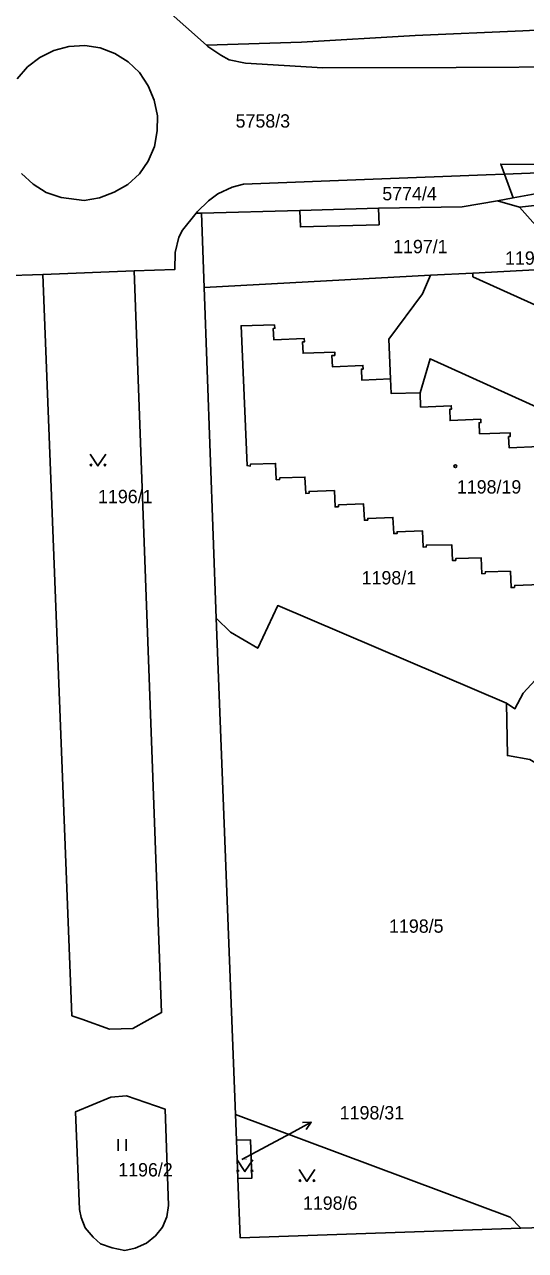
# Model space of a CAD drawing. Extents: x -737240 to -735272, y -1119606 to -1117878.
# Drawn here: x -736364.4 to -736300.4, y -1118991.4 to -1118834.9 of the extents above; entities that cross this region are included whole.
import ezdxf

# ---------------------------------------------------------------- set-up
doc = ezdxf.new("R2010")
doc.units = 0
for name, color, linetype in [('Level 1', 7, 'Continuous'), ('Level 16', 7, 'Continuous'), ('Level 18', 7, 'Continuous'), ('Level 19', 7, 'Continuous'), ('Level 25', 7, 'Continuous'), ('Level 4', 7, 'Continuous')]:
    doc.layers.add(name, color=color, linetype=linetype)

msp = doc.modelspace()

# ---------------------------------------------------------------- linework, layer by layer
at = {"layer": 'Level 1'}
for p, q in [((-736302.01, -1118857.02), (-736279.15, -1118852.89)), ((-736302.01, -1118857.02), (-736303.13, -1118854)), ((-736304.02, -1118857.38), (-736302.01, -1118857.02)), ((-736304.02, -1118857.38), (-736301.2, -1118858.22)), ((-736342.5, -1118858.98), (-736341.8, -1118858.99)), ((-736341.8, -1118858.99), (-736329.24, -1118858.62)), ((-736341.45, -1118868.44), (-736341.8, -1118858.99)), ((-736294.23, -1118865.92), (-736307.17, -1118866.61)), ((-736362.05, -1118866.78), (-736350.38, -1118866.35)), ((-736312.56, -1118866.9), (-736341.45, -1118868.44)), ((-736307.17, -1118866.61), (-736312.56, -1118866.9)), ((-736339.93, -1118910.64), (-736341.45, -1118868.44)), ((-736337.48, -1118973.99), (-736339.93, -1118910.64)), ((-736337.35, -1118977.29), (-736337.48, -1118973.99)), ((-736337.35, -1118977.29), (-736337.16, -1118982.18)), ((-736280.9, -1118987.85), (-736301.04, -1118988.52))]:
    msp.add_line(p, q, dxfattribs=at)
for points in [[(-736341.17, -1118837.53), (-736343.79, -1118835.17), (-736346.04, -1118833.2), (-736346.85, -1118832.56), (-736349.46, -1118831.04), (-736352.7, -1118828.71), (-736353.4, -1118828), (-736355.31, -1118825.68), (-736355.71, -1118824.8), (-736361.77, -1118826.39)], [(-736270.78, -1118834.19), (-736278.9, -1118834.59), (-736300.78, -1118835.7), (-736314.51, -1118836.31), (-736329.03, -1118837.15), (-736341.17, -1118837.53)], [(-736275.1, -1118839.95), (-736287.83, -1118840.38), (-736293.27, -1118840.3), (-736309.28, -1118840.36), (-736326.31, -1118840.44), (-736336.17, -1118839.81), (-736338.26, -1118839.41), (-736339.35, -1118838.81), (-736341.01, -1118837.68), (-736341.17, -1118837.53)], [(-736303.13, -1118854), (-736303.61, -1118852.71), (-736286.16, -1118852.84)], [(-736303.13, -1118854), (-736287.83, -1118853.38), (-736286.16, -1118852.84)], [(-736342.5, -1118858.98), (-736342.35, -1118858.8), (-736340.89, -1118857.4), (-736339.73, -1118856.5), (-736337.88, -1118855.67), (-736336.43, -1118855.25), (-736319.9, -1118854.62), (-736305.45, -1118854.09), (-736303.13, -1118854)], [(-736319.19, -1118858.34), (-736308.54, -1118858.15), (-736304.02, -1118857.38)], [(-736294.02, -1118858.75), (-736296.65, -1118857.69), (-736301.2, -1118858.22)], [(-736371.48, -1118858.67), (-736369.78, -1118860.4), (-736368.64, -1118862.08), (-736368.28, -1118863.06), (-736367.4, -1118866.97), (-736362.05, -1118866.78)], [(-736350.38, -1118866.35), (-736345.22, -1118866.16), (-736345.16, -1118863.99), (-736344.68, -1118862.04), (-736344.22, -1118861.14), (-736342.5, -1118858.98)], [(-736329.24, -1118858.62), (-736329.18, -1118860.72), (-736319.13, -1118860.44), (-736319.19, -1118858.34)], [(-736301.2, -1118858.22), (-736297.75, -1118862.09), (-736294.23, -1118865.92)], [(-736350.38, -1118866.35), (-736346.91, -1118960.99), (-736350.58, -1118963.04), (-736353.55, -1118963.11), (-736357.09, -1118961.84), (-736358.35, -1118961.4), (-736362.05, -1118866.78)], [(-736312.56, -1118866.9), (-736313.59, -1118869.28), (-736317.9, -1118875.05), (-736317.67, -1118880.13)], [(-736307.17, -1118866.61), (-736307.16, -1118867.08), (-736292.73, -1118873.59), (-736288.98, -1118875.29), (-736286.65, -1118874.25), (-736286.5, -1118873.95)], [(-736317.67, -1118880.13), (-736321.34, -1118880.28), (-736321.4, -1118878.87), (-736321.17, -1118878.86), (-736321.19, -1118878.41), (-736325.1, -1118878.58), (-736325.16, -1118877.13), (-736324.79, -1118877.12), (-736324.8, -1118876.69), (-736328.84, -1118876.85), (-736328.9, -1118875.41), (-736328.66, -1118875.4), (-736328.69, -1118874.98), (-736332.58, -1118875.12), (-736332.64, -1118873.67), (-736332.44, -1118873.66), (-736332.49, -1118873.23), (-736336.76, -1118873.34), (-736335.99, -1118891.19), (-736335.59, -1118891.24), (-736335.57, -1118891.01), (-736332.35, -1118890.9), (-736332.26, -1118893), (-736331.84, -1118892.96), (-736331.82, -1118892.76), (-736328.6, -1118892.65), (-736328.5, -1118894.73), (-736328.08, -1118894.71), (-736328.06, -1118894.48), (-736324.83, -1118894.37), (-736324.75, -1118896.45), (-736324.33, -1118896.43), (-736324.3, -1118896.2), (-736321.12, -1118896.08), (-736321, -1118898.16), (-736320.58, -1118898.14), (-736320.59, -1118897.92), (-736317.36, -1118897.79), (-736317.26, -1118899.87), (-736316.83, -1118899.86), (-736316.83, -1118899.62), (-736313.6, -1118899.49), (-736313.51, -1118901.59), (-736313.11, -1118901.57), (-736313.09, -1118901.33), (-736309.85, -1118901.28), (-736309.75, -1118903.3), (-736309.35, -1118903.28), (-736309.32, -1118903.04), (-736306.1, -1118902.96), (-736306, -1118904.98), (-736305.6, -1118904.97), (-736305.56, -1118904.74), (-736302.36, -1118904.67), (-736302.28, -1118906.76), (-736301.86, -1118906.74), (-736301.82, -1118906.48), (-736298.57, -1118906.37)], [(-736313.9, -1118881.88), (-736312.63, -1118877.55), (-736279.57, -1118892.52), (-736277.38, -1118894.72), (-736275.95, -1118897.46), (-736275.25, -1118902.06), (-736280.14, -1118912.96), (-736283.92, -1118913.89), (-736289.94, -1118914.19), (-736293.05, -1118914.65), (-736295.79, -1118915.81), (-736298.2, -1118917.45), (-736300.75, -1118920.21), (-736301.8, -1118922.21), (-736302.86, -1118921.51)], [(-736317.67, -1118880.13), (-736317.59, -1118882), (-736313.9, -1118881.88)], [(-736302.6, -1118887.46), (-736302.38, -1118887.45), (-736302.4, -1118887.01), (-736306.31, -1118887.13), (-736306.36, -1118885.71), (-736306.14, -1118885.7), (-736306.15, -1118885.26), (-736310.06, -1118885.43), (-736310.12, -1118884), (-736309.9, -1118883.99), (-736309.92, -1118883.55), (-736313.83, -1118883.72), (-736313.9, -1118881.88)], [(-736298.65, -1118888.73), (-736302.53, -1118888.91), (-736302.6, -1118887.46)], [(-736302.86, -1118921.51), (-736332.07, -1118909.05), (-736334.62, -1118914.5), (-736338.12, -1118912.46), (-736339.93, -1118910.64)], [(-736302.86, -1118921.51), (-736302.75, -1118928.2), (-736299.88, -1118928.69), (-736298.09, -1118929.74), (-736296.98, -1118931.46), (-736296.61, -1118933.2)], [(-736357.38, -1118986.12), (-736357.87, -1118973.64), (-736353.37, -1118971.78), (-736351.38, -1118971.63), (-736346.46, -1118973.31), (-736346.01, -1118985.59), (-736346.23, -1118987.06), (-736346.8, -1118988.39), (-736347.69, -1118989.47), (-736348.84, -1118990.43), (-736350.28, -1118991.04), (-736351.61, -1118991.35), (-736353.23, -1118991), (-736354.69, -1118990.51), (-736355.64, -1118989.66), (-736356.65, -1118988.44), (-736357.17, -1118987.15), (-736357.38, -1118986.12)], [(-736301.04, -1118988.52), (-736302.41, -1118987.09), (-736337.48, -1118973.99)], [(-736337.16, -1118982.18), (-736335.36, -1118982.11), (-736335.55, -1118977.22), (-736337.35, -1118977.29)], [(-736301.04, -1118988.52), (-736336.87, -1118989.72), (-736337.16, -1118982.18)]]:
    msp.add_lwpolyline(points, dxfattribs=at)
at = {"layer": 'Level 16'}
for points in [[(-736336.65, -1118979.75), (-736330.43, -1118976.4), (-736327.789, -1118974.977)], [(-736328.907, -1118975.011), (-736327.789, -1118974.977), (-736328.432, -1118975.891)]]:
    msp.add_lwpolyline(points, dxfattribs=at)
at = {"layer": 'Level 25'}
for p, q in [((-736352.457, -1118977.135), (-736352.457, -1118978.635)), ((-736351.435, -1118978.635), (-736351.435, -1118977.135))]:
    msp.add_line(p, q, dxfattribs=at)
for points in [[(-736354.02, -1118889.72), (-736355.02, -1118891.22), (-736356.02, -1118889.72)], [(-736335.27, -1118979.78), (-736336.27, -1118981.28), (-736337.27, -1118979.78)], [(-736327.34, -1118981.03), (-736328.34, -1118982.53), (-736329.34, -1118981.03)]]:
    msp.add_lwpolyline(points, dxfattribs=at)
for centre in [(-736355.92, -1118891.12), (-736354.12, -1118891.12), (-736337.17, -1118981.18), (-736335.37, -1118981.18), (-736329.24, -1118982.43), (-736327.44, -1118982.43)]:
    msp.add_circle(centre, 0.1, dxfattribs=at)
msp.add_ellipse((-736309.4, -1118891.27), major_axis=(0.18, 0), ratio=0.9848078, dxfattribs=at)
at = {"layer": 'Level 4'}
msp.add_line((-736329.24, -1118858.62), (-736319.19, -1118858.34), dxfattribs=at)
for points in [[(-736358.73, -1118837.71), (-736360.67, -1118838.19), (-736362.44, -1118839.1), (-736364.02, -1118840.31), (-736365.33, -1118841.82)], [(-736364.79, -1118853.92), (-736363.3, -1118855.27), (-736361.63, -1118856.33), (-736359.74, -1118856.98), (-736356.78, -1118857.34), (-736354.81, -1118857.03), (-736352.94, -1118856.29), (-736351.21, -1118855.3), (-736349.73, -1118853.94), (-736348.6, -1118852.32), (-736347.8, -1118850.48), (-736347.46, -1118848.48), (-736347.42, -1118846.54), (-736347.86, -1118844.57), (-736348.63, -1118842.7), (-736349.73, -1118841.03), (-736351.18, -1118839.66), (-736352.87, -1118838.59), (-736354.74, -1118837.87), (-736356.71, -1118837.58), (-736358.73, -1118837.71)]]:
    msp.add_lwpolyline(points, dxfattribs=at)

# ---------------------------------------------------------------- texts
at = {"layer": 'Level 16'}
for s, p in [('1197/4', (-736303.05, -1118865.55)), ('1198/31', (-736324.155, -1118974.62))]:
    msp.add_text(s, height=1.7, dxfattribs=at).set_placement(p)
at = {"layer": 'Level 18'}
for s, height, p in [('5758/3', 1.7, (-736337.45, -1118848.05)), ('5774/4', 1.7, (-736318.72, -1118857.33)), ('1197/1', 1.7, (-736317.34, -1118864.08)), ('1196/1', 1.7, (-736355.01, -1118895.98)), ('1198/1', 1.7, (-736321.36, -1118906.35)), ('1198/5', 1.7, (-736317.86, -1118950.8)), ('1196/2', 1.7, (-736352.43, -1118981.9)), ('1198/31', 0.1, (-736336.475, -1118979.75)), ('1198/6', 1.7, (-736328.85, -1118986.15))]:
    msp.add_text(s, height=height, dxfattribs=at).set_placement(p)
at = {"layer": 'Level 19'}
msp.add_text('1198/19', height=1.7, dxfattribs=at).set_placement((-736309.2, -1118894.75))

doc.saveas('drawing.dxf')
